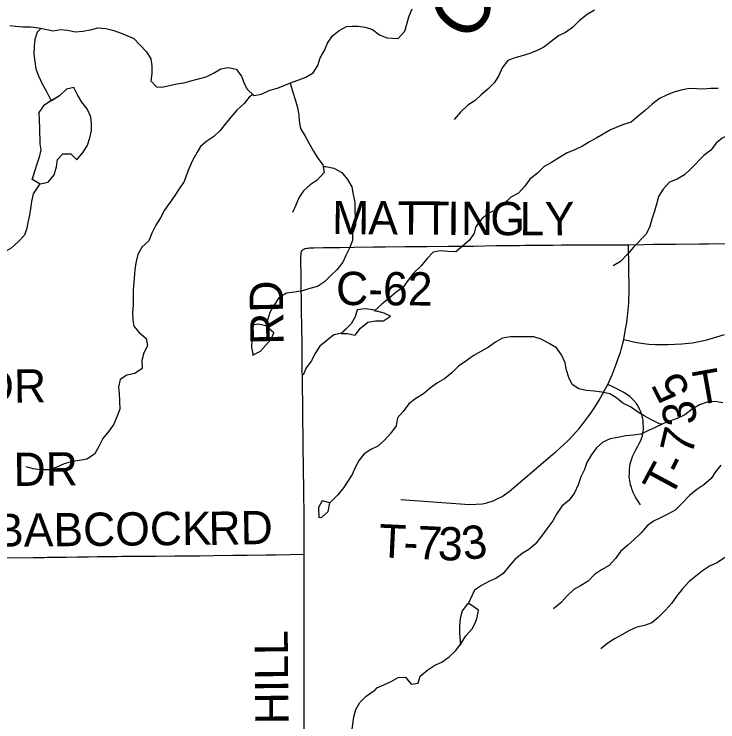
# Model space of a CAD drawing. Extents: x 0 to 34, y 0 to 22.
# Drawn here: x 6.998 to 7.598, y 19.547 to 20.151 of the extents above; entities that cross this region are included whole.
import ezdxf

# ---------------------------------------------------------------- set-up
doc = ezdxf.new("R2010")
doc.units = 0
for name, color, linetype in [('GM_X_County_Road', 7, 'Continuous'), ('GM_X_County_Road_Text', 7, 'Continuous'), ('GM_X_Minor_Lake', 7, 'Continuous'), ('GM_X_Minor_River', 7, 'Continuous'), ('GM_X_Minor_River_Text', 7, 'Continuous'), ('GM_X_Township_Road', 7, 'Continuous'), ('GM_X_Township_Road_Text', 7, 'Continuous')]:
    doc.layers.add(name, color=color, linetype=linetype)

msp = doc.modelspace()

# ---------------------------------------------------------------- linework, layer by layer
at = {"layer": 'GM_X_County_Road'}
for points in [[(7.24366, 19.94905), (7.2443, 19.94977), (7.24497, 19.95028), (7.24573, 19.95066), (7.2465, 19.95087), (7.24755, 19.95108), (7.24865, 19.95117), (7.24983, 19.95125), (7.25135, 19.95129), (7.25355, 19.95136), (7.26175, 19.95146), (7.27591, 19.95168), (7.28804, 19.95193), (7.3046, 19.95214), (7.31483, 19.95227), (7.33145, 19.95233), (7.34095, 19.95239), (7.35041, 19.95248), (7.36812, 19.95265), (7.37995, 19.95273), (7.38993, 19.95286), (7.4089, 19.95317), (7.41423, 19.95323), (7.42078, 19.9533), (7.42902, 19.95345), (7.43371, 19.95349), (7.4425, 19.95353), (7.45021, 19.95362), (7.4575, 19.95366), (7.46507, 19.95374), (7.49066, 19.95378), (7.51308, 19.95396), (7.51899, 19.95401), (7.52228, 19.95401), (7.53535, 19.95425), (7.54364, 19.95433), (7.5629, 19.95456), (7.58271, 19.95464), (7.59039, 19.95474), (7.61189, 19.95488)], [(7.24535, 19.6897), (7.24527, 19.72849), (7.24514, 19.7375), (7.24502, 19.74903), (7.24485, 19.75841), (7.24463, 19.76813), (7.24451, 19.77743), (7.24438, 19.78796), (7.24417, 19.80697), (7.24408, 19.8232), (7.24396, 19.82721), (7.24379, 19.83918), (7.24366, 19.8483), (7.24362, 19.85452), (7.24349, 19.86969), (7.24307, 19.89779), (7.24278, 19.92585), (7.24248, 19.94187), (7.24269, 19.9472), (7.24311, 19.94821), (7.24366, 19.94905)], [(7.2459, 19.17375), (7.24566, 19.20527), (7.24553, 19.29971), (7.2454, 19.39006), (7.24549, 19.40607), (7.24531, 19.49947), (7.24522, 19.61935), (7.24535, 19.65145), (7.24535, 19.6897)]]:
    msp.add_lwpolyline(points, dxfattribs=at)
at = {"layer": 'GM_X_Minor_Lake'}
for points in [[(7.01291, 20.01009), (7.01989, 20.00585), (7.02669, 20.0073), (7.03189, 20.01367), (7.03384, 20.02055), (7.03467, 20.02684), (7.03933, 20.03167), (7.04597, 20.03161), (7.05119, 20.02657), (7.05657, 20.03294), (7.06026, 20.0389), (7.06241, 20.04521), (7.06363, 20.05151), (7.06371, 20.05721), (7.06303, 20.06328), (7.06006, 20.06987), (7.0554, 20.07568), (7.05186, 20.08207), (7.04852, 20.08809), (7.04229, 20.08665), (7.03632, 20.08102), (7.02957, 20.07691)], [(7.01307, 20.00999), (7.01989, 20.00585), (7.02669, 20.0073), (7.03189, 20.01367), (7.03384, 20.02055), (7.03467, 20.02684), (7.03933, 20.03167), (7.04597, 20.03161), (7.05119, 20.02657), (7.05657, 20.03294), (7.06026, 20.0389), (7.06241, 20.04521), (7.06363, 20.05151), (7.06371, 20.05721), (7.06303, 20.06328), (7.06006, 20.06987), (7.0554, 20.07568), (7.05186, 20.08207), (7.04852, 20.08809), (7.04229, 20.08665), (7.03632, 20.08102), (7.02732, 20.07554)], [(7.02732, 20.07554), (7.02282, 20.07241), (7.01875, 20.06682), (7.01907, 20.05999), (7.01938, 20.05353), (7.01963, 20.04005), (7.02048, 20.03512), (7.01908, 20.02864), (7.01711, 20.02271), (7.01514, 20.0164), (7.01307, 20.00999)], [(7.02956, 20.0771), (7.02282, 20.07241), (7.01875, 20.06682), (7.01907, 20.05999), (7.01938, 20.05353), (7.01963, 20.04005), (7.02048, 20.03512), (7.01908, 20.02864), (7.01711, 20.02271), (7.01514, 20.0164), (7.01316, 20.01028)], [(7.30537, 19.89772), (7.30384, 19.89845), (7.297, 19.89927), (7.29056, 19.89839), (7.28878, 19.89228), (7.28528, 19.88632), (7.27687, 19.87814)], [(7.27687, 19.87832), (7.28202, 19.87809), (7.28888, 19.8767), (7.29351, 19.88286), (7.29968, 19.88773), (7.30611, 19.88899), (7.31294, 19.88912), (7.31894, 19.89284), (7.31357, 19.89559), (7.30501, 19.89743)], [(7.30537, 19.89772), (7.30384, 19.89845), (7.297, 19.89927), (7.29056, 19.89839), (7.28878, 19.89228), (7.28528, 19.88632), (7.27704, 19.87831)], [(7.27704, 19.87831), (7.28202, 19.87809), (7.28888, 19.8767), (7.29351, 19.88286), (7.29968, 19.88773), (7.30611, 19.88899), (7.31294, 19.88912), (7.31894, 19.89284), (7.31357, 19.89559), (7.30537, 19.89772)], [(7.21262, 19.88471), (7.20635, 19.88618), (7.19974, 19.88492), (7.20081, 19.87848), (7.20073, 19.87239), (7.20046, 19.86631), (7.20167, 19.85994)], [(7.21262, 19.88471), (7.20635, 19.88618), (7.19974, 19.88492), (7.20081, 19.87848), (7.20073, 19.87239), (7.20046, 19.86631), (7.20173, 19.85968)], [(7.20129, 19.85976), (7.20792, 19.86303), (7.2122, 19.86786), (7.21722, 19.87327), (7.21935, 19.87887), (7.21298, 19.88506)], [(7.20167, 19.85994), (7.20792, 19.86303), (7.2122, 19.86786), (7.21722, 19.87327), (7.21935, 19.87887), (7.21262, 19.88471)], [(7.26715, 19.73367), (7.26052, 19.73518), (7.25746, 19.7296), (7.25781, 19.72122)], [(7.2671, 19.73368), (7.26052, 19.73518), (7.25746, 19.7296), (7.25781, 19.72122)], [(7.25775, 19.72122), (7.26046, 19.72129), (7.26587, 19.72633), (7.26716, 19.73368)], [(7.25781, 19.72122), (7.26046, 19.72129), (7.26587, 19.72633), (7.26715, 19.73367)], [(7.38668, 19.6471), (7.3846, 19.6474), (7.38016, 19.64143), (7.37857, 19.63494), (7.37793, 19.62866), (7.37786, 19.62219), (7.37869, 19.61229)], [(7.38689, 19.64707), (7.3846, 19.6474), (7.38016, 19.64143), (7.37857, 19.63494), (7.37793, 19.62866), (7.37786, 19.62219), (7.37862, 19.61316)], [(7.37869, 19.61229), (7.37953, 19.61405), (7.38322, 19.62001), (7.38861, 19.626), (7.39117, 19.6308), (7.39298, 19.63559), (7.39419, 19.64207), (7.38668, 19.6471)], [(7.3788, 19.61252), (7.37953, 19.61405), (7.38322, 19.62001), (7.38861, 19.626), (7.39117, 19.6308), (7.39298, 19.63559), (7.39419, 19.64207), (7.38671, 19.64708)]]:
    msp.add_lwpolyline(points, dxfattribs=at)
at = {"layer": 'GM_X_Minor_River'}
for points in [[(7.20234, 20.08127), (7.20896, 20.08253), (7.21592, 20.08589), (7.22253, 20.08753), (7.22874, 20.09031), (7.23496, 20.09271), (7.24061, 20.09471), (7.24664, 20.0971), (7.25302, 20.10064), (7.25689, 20.10699), (7.25885, 20.11367), (7.26253, 20.11982), (7.26507, 20.12614), (7.26951, 20.13231), (7.27531, 20.13697), (7.2815, 20.14032), (7.28624, 20.1406), (7.29099, 20.1405), (7.29726, 20.13985), (7.30356, 20.13769), (7.30972, 20.13325), (7.31584, 20.1307), (7.32059, 20.13041), (7.32553, 20.13012), (7.3311, 20.1363), (7.33308, 20.14223), (7.33467, 20.14853), (7.33739, 20.15542)], [(7.49319, 20.15433), (7.48681, 20.15041), (7.48026, 20.14535), (7.47449, 20.13954), (7.4685, 20.13506), (7.46229, 20.13228), (7.44995, 20.12255), (7.44431, 20.11979), (7.4379, 20.1172), (7.4313, 20.11518), (7.42507, 20.11354), (7.41904, 20.11115), (7.41441, 20.10498), (7.4115, 20.09846), (7.40781, 20.0925), (7.40223, 20.0867), (7.39644, 20.08184), (7.39122, 20.07699), (7.38503, 20.07308), (7.37868, 20.06726), (7.37349, 20.06089)], [(6.99403, 20.14105), (6.99897, 20.14057), (7.00506, 20.13992), (7.01189, 20.13986), (7.01836, 20.13903), (7.02426, 20.138), (7.03111, 20.13661), (7.03736, 20.13767), (7.04344, 20.13703), (7.04992, 20.13563), (7.05635, 20.13632), (7.06279, 20.13739), (7.06921, 20.13903), (7.07605, 20.13858), (7.08272, 20.137), (7.08903, 20.13445), (7.0938, 20.13264), (7.09974, 20.1299), (7.10496, 20.12468), (7.11076, 20.11871), (7.11448, 20.11269), (7.11535, 20.10663), (7.11528, 20.10017), (7.11445, 20.09388), (7.1191, 20.08865), (7.12385, 20.08835), (7.13027, 20.09), (7.13669, 20.09144), (7.14256, 20.09232), (7.1486, 20.09376), (7.15521, 20.09559), (7.16163, 20.09723), (7.16783, 20.10039), (7.17421, 20.10412), (7.18045, 20.10537), (7.18712, 20.10379), (7.19179, 20.09779), (7.19418, 20.09157), (7.19674, 20.08667), (7.20234, 20.08127)], [(7.02008, 20.1383), (7.01747, 20.1354), (7.01531, 20.12928), (7.01466, 20.12338), (7.0146, 20.11673), (7.01529, 20.11028), (7.01616, 20.10402), (7.01836, 20.09817), (7.02132, 20.09177), (7.02505, 20.08537), (7.02917, 20.0767)], [(7.23345, 20.09211), (7.23366, 20.09097), (7.23549, 20.08416), (7.23751, 20.07793), (7.23953, 20.07113), (7.2406, 20.06469), (7.24088, 20.05975), (7.24214, 20.05331), (7.24625, 20.04655), (7.24959, 20.04034), (7.25313, 20.03394), (7.25684, 20.02793), (7.26113, 20.02212), (7.26239, 20.01549), (7.25644, 20.00911), (7.25044, 20.0052), (7.24465, 19.99996), (7.24078, 19.994), (7.23824, 19.98787), (7.23532, 19.98135)], [(7.59879, 20.08732), (7.59234, 20.08739), (7.58552, 20.08688), (7.58077, 20.08698), (7.57394, 20.08724), (7.56713, 20.08597), (7.5609, 20.08433), (7.55469, 20.08156), (7.54867, 20.07879), (7.5423, 20.07411), (7.53671, 20.06887), (7.53054, 20.06382), (7.52438, 20.05857), (7.51796, 20.05655), (7.51175, 20.05396), (7.50685, 20.05197), (7.50066, 20.04844), (7.49503, 20.0451), (7.48902, 20.04195), (7.48282, 20.03822), (7.47624, 20.03487), (7.46984, 20.03247), (7.46327, 20.02836), (7.45652, 20.02405), (7.45014, 20.0207), (7.44436, 20.01508), (7.438, 20.00983), (7.43356, 20.00386), (7.42836, 19.99806), (7.42178, 19.99452), (7.416, 19.98928), (7.40965, 19.98384), (7.40325, 19.98106), (7.39689, 19.976), (7.39189, 19.96964), (7.39029, 19.96372), (7.38604, 19.95756), (7.38044, 19.9527), (7.37483, 19.94804), (7.368, 19.94829), (7.36173, 19.94874), (7.35549, 19.94749), (7.35009, 19.94188), (7.34527, 19.9359), (7.33855, 19.92969), (7.33411, 19.92372), (7.32986, 19.91775), (7.32349, 19.91326), (7.31752, 19.90801), (7.31153, 19.90315), (7.30556, 19.89772)], [(7.20139, 20.08213), (7.19838, 20.07986), (7.19393, 20.07446), (7.18777, 20.06883), (7.18257, 20.06285), (7.17794, 20.05687), (7.17368, 20.05147), (7.16808, 20.04623), (7.16208, 20.04251), (7.15685, 20.03785), (7.15391, 20.03305), (7.14987, 20.02594), (7.14678, 20.01866), (7.14442, 20.01273), (7.1428, 20.00795), (7.13855, 20.00179), (7.13431, 19.99506), (7.12618, 19.9835), (7.12251, 19.97697), (7.11864, 19.97063), (7.11535, 19.96392), (7.11262, 19.95741), (7.10666, 19.95178), (7.10336, 19.94564), (7.10195, 19.93972), (7.10074, 19.93324), (7.10045, 19.92848), (7.09981, 19.92201), (7.09937, 19.91516), (7.0993, 19.90851), (7.09923, 19.90243), (7.09878, 19.89615), (7.0989, 19.88969), (7.09994, 19.88458), (7.10402, 19.87933), (7.11038, 19.87394), (7.11164, 19.86769), (7.10834, 19.86155), (7.10675, 19.85506), (7.10707, 19.84823), (7.1007, 19.84393), (7.09389, 19.84266), (7.08827, 19.83894), (7.08687, 19.83265), (7.08735, 19.82696), (7.08766, 19.8205), (7.08779, 19.81366), (7.08544, 19.80716), (7.08271, 19.80083), (7.07847, 19.79468), (7.07346, 19.7885), (7.06998, 19.78178), (7.0663, 19.77525), (7.05975, 19.77076), (7.05312, 19.76988), (7.04631, 19.76861), (7.04047, 19.76679), (7.03426, 19.76402), (7.02728, 19.7618), (7.02045, 19.76167), (7.01398, 19.7625), (7.00787, 19.76448)], [(7.61368, 20.05003), (7.61341, 20.04988), (7.60806, 20.04778), (7.60224, 20.04482), (7.597, 20.04073), (7.59256, 20.03476), (7.58657, 20.03008), (7.5754, 20.01885), (7.56999, 20.01362), (7.56361, 20.01008), (7.55721, 20.0073), (7.55181, 20.0015), (7.54776, 19.99516), (7.54617, 19.98866), (7.54439, 19.98255), (7.54224, 19.97586), (7.54027, 19.96955), (7.53716, 19.96303), (7.52655, 19.952), (7.52135, 19.94583), (7.5154, 19.93963), (7.50901, 19.93609)], [(7.2621, 20.02062), (7.26381, 20.02084), (7.27066, 20.01945), (7.27737, 20.01577), (7.28223, 20.00959), (7.28595, 20.00339), (7.28721, 19.99676), (7.28867, 19.98995), (7.2886, 19.98368), (7.28891, 19.97684), (7.28903, 19.97038), (7.28669, 19.96369), (7.28642, 19.9576), (7.28389, 19.95109), (7.28097, 19.94477), (7.27823, 19.93902), (7.2736, 19.93285), (7.268, 19.92781), (7.26261, 19.92219), (7.25661, 19.91828), (7.25019, 19.91664), (7.24377, 19.91462), (7.23715, 19.91355), (7.23015, 19.91266), (7.22377, 19.90855), (7.21934, 19.90219), (7.21603, 19.89624), (7.21262, 19.88471)], [(7.01973, 20.00586), (7.01378, 19.99737), (7.01258, 19.99089), (7.01174, 19.98479), (7.0109, 19.97907), (7.00949, 19.97297), (7.00863, 19.9682), (7.00666, 19.96208), (7.00107, 19.95647), (6.9951, 19.95104), (6.9891, 19.9475), (6.9835, 19.94227), (6.97907, 19.93573), (6.97802, 19.93095), (6.97815, 19.92412), (6.97865, 19.91728), (6.98068, 19.91048)], [(7.27746, 19.87838), (7.27066, 19.87712), (7.25869, 19.86739), (7.25445, 19.86085), (7.25153, 19.85472), (7.24689, 19.84893), (7.24435, 19.84261)], [(7.55081, 19.80081), (7.54852, 19.80115), (7.54182, 19.80444), (7.5355, 19.80775), (7.52974, 19.81125), (7.52378, 19.81551), (7.51746, 19.81881), (7.51226, 19.8229), (7.50631, 19.82659), (7.49945, 19.82798), (7.49298, 19.82881), (7.48633, 19.82964), (7.47985, 19.83084), (7.47409, 19.83454), (7.47113, 19.84075), (7.46931, 19.84699), (7.46805, 19.85324), (7.46489, 19.85983), (7.46079, 19.86603), (7.45447, 19.86952), (7.44756, 19.87338), (7.44127, 19.87535), (7.43443, 19.87542), (7.42799, 19.8753), (7.42153, 19.87537), (7.41473, 19.8741), (7.40872, 19.87076), (7.40272, 19.86665), (7.39615, 19.86273), (7.38958, 19.859), (7.38321, 19.8547), (7.37703, 19.8504), (7.37144, 19.8446), (7.36509, 19.83954), (7.35908, 19.8362), (7.35328, 19.83191), (7.3473, 19.82667), (7.34073, 19.82274), (7.33456, 19.81826), (7.32974, 19.81171), (7.32511, 19.80611), (7.32371, 19.79943), (7.31928, 19.79308), (7.3137, 19.78689), (7.3081, 19.78185), (7.30227, 19.77908), (7.29646, 19.77536), (7.29219, 19.77015), (7.28907, 19.76439), (7.28616, 19.75788), (7.28192, 19.75115), (7.27897, 19.74634), (7.27396, 19.74055), (7.26721, 19.73365)], [(7.60265, 19.81907), (7.59617, 19.82009), (7.58935, 19.81958), (7.58295, 19.81718), (7.57656, 19.81364), (7.5702, 19.80877), (7.56381, 19.80561), (7.55721, 19.8034), (7.55156, 19.80102), (7.54498, 19.79785), (7.53933, 19.79528), (7.53275, 19.7923), (7.52613, 19.79142), (7.51987, 19.79092), (7.51307, 19.78947), (7.50664, 19.78821), (7.50024, 19.78543), (7.49483, 19.78058), (7.49021, 19.77422), (7.48671, 19.76807), (7.48455, 19.76195), (7.48163, 19.75582), (7.47929, 19.74893), (7.476, 19.74203), (7.47156, 19.73587), (7.46521, 19.73081), (7.46059, 19.72407), (7.45748, 19.71812), (7.45248, 19.71138), (7.44785, 19.70502), (7.44247, 19.69846), (7.43706, 19.6938), (7.43143, 19.69046), (7.42526, 19.68522), (7.42006, 19.67923), (7.41524, 19.67325), (7.40905, 19.66914), (7.40303, 19.66656), (7.39665, 19.66302), (7.39084, 19.65892), (7.38509, 19.64685)], [(7.60098, 19.76583), (7.59653, 19.76005), (7.59266, 19.75427), (7.58649, 19.74903), (7.58049, 19.74512), (7.57414, 19.73987), (7.56838, 19.73349), (7.56204, 19.72748), (7.55584, 19.72394), (7.54945, 19.72078), (7.54343, 19.71782), (7.53819, 19.71392), (7.53299, 19.70812), (7.5274, 19.70251), (7.52161, 19.69746), (7.51545, 19.69203), (7.5112, 19.68606), (7.5058, 19.68025), (7.49923, 19.67652), (7.49324, 19.67242), (7.48765, 19.6668), (7.48128, 19.66269), (7.47545, 19.65955), (7.46986, 19.65431), (7.46484, 19.64852), (7.4583, 19.64307)], [(7.61617, 19.69409), (7.61636, 19.6941), (7.60997, 19.69056), (7.60398, 19.68626), (7.5976, 19.68234), (7.59139, 19.67957), (7.58539, 19.67566), (7.5796, 19.67099), (7.57399, 19.66632), (7.56841, 19.66014), (7.56359, 19.65416), (7.55878, 19.6478), (7.55376, 19.642), (7.54743, 19.63561), (7.54201, 19.63114), (7.53579, 19.62875), (7.52937, 19.62748), (7.52316, 19.62471), (7.5164, 19.62097), (7.5102, 19.61744), (7.50457, 19.61391), (7.49859, 19.60905)], [(7.30591, 19.57354), (7.3072, 19.57565), (7.31341, 19.57824), (7.31943, 19.58101), (7.32544, 19.58454), (7.33188, 19.58485), (7.33674, 19.57867), (7.34261, 19.57954), (7.34439, 19.58565), (7.35074, 19.59109), (7.35674, 19.59501), (7.36276, 19.59759), (7.36913, 19.60227), (7.37453, 19.60731), (7.37917, 19.6131)], [(7.22827, 19.48144), (7.24372, 19.49143), (7.24975, 19.49249), (7.25576, 19.49525), (7.26173, 19.49953), (7.26712, 19.50512), (7.26889, 19.5118), (7.27108, 19.51658), (7.27743, 19.52124), (7.28226, 19.52607), (7.28405, 19.53217), (7.28602, 19.53847), (7.28686, 19.54437), (7.28769, 19.55102), (7.28928, 19.55731), (7.29277, 19.56325), (7.29835, 19.56848), (7.30565, 19.57377)]]:
    msp.add_lwpolyline(points, dxfattribs=at)
at = {"layer": 'GM_X_Township_Road'}
for points in [[(7.3277, 19.73635), (7.38656, 19.73228), (7.39744, 19.73275), (7.4012, 19.73353), (7.4066, 19.73518), (7.41074, 19.73719), (7.41439, 19.73908), (7.42039, 19.7434), (7.45739, 19.77486), (7.46029, 19.77728), (7.46319, 19.77987), (7.4671, 19.78347), (7.47062, 19.78684), (7.47532, 19.79168), (7.48001, 19.79701), (7.48314, 19.80092), (7.48745, 19.80663), (7.4905, 19.81094), (7.49394, 19.8161), (7.49715, 19.82127), (7.50004, 19.8263), (7.50238, 19.83053), (7.5046, 19.83475), (7.50819, 19.84295), (7.50991, 19.84733), (7.51163, 19.85187), (7.51343, 19.85688), (7.51523, 19.8622), (7.51591, 19.86464), (7.51672, 19.86745), (7.51741, 19.87001), (7.51821, 19.87293), (7.51977, 19.88177), (7.52079, 19.88748), (7.52165, 19.89547), (7.52236, 19.90416), (7.52267, 19.91566), (7.52228, 19.95401)], [(7.51821, 19.87293), (7.52431, 19.87152), (7.52776, 19.87081), (7.53292, 19.86987), (7.53965, 19.86909), (7.54529, 19.86878), (7.55593, 19.86886), (7.5618, 19.86909), (7.56775, 19.86933), (7.57339, 19.86995), (7.57683, 19.87034), (7.58106, 19.87105), (7.58505, 19.87191), (7.5892, 19.87285), (7.59757, 19.87527), (7.60407, 19.87723)], [(7.53239, 19.73183), (7.52975, 19.73575), (7.52821, 19.73844), (7.52621, 19.74253), (7.52532, 19.74483), (7.52464, 19.74692), (7.52404, 19.74897), (7.52353, 19.75089), (7.52323, 19.75276), (7.52301, 19.75434), (7.52289, 19.7557), (7.52293, 19.75877), (7.5231, 19.7624), (7.52335, 19.76457), (7.5237, 19.76683), (7.5241, 19.76848), (7.52464, 19.77028), (7.52566, 19.7731), (7.52724, 19.77655), (7.52867, 19.77941), (7.53026, 19.78205), (7.53141, 19.78423), (7.53252, 19.78636), (7.53338, 19.78866), (7.53402, 19.79092), (7.53452, 19.79301), (7.53478, 19.79484), (7.53491, 19.79655), (7.53474, 19.80324), (7.53435, 19.80571), (7.53393, 19.80742), (7.53355, 19.80891), (7.53265, 19.81134), (7.53167, 19.81364), (7.53039, 19.81603), (7.52894, 19.81829), (7.52638, 19.82136), (7.52357, 19.82413), (7.5205, 19.82639), (7.51769, 19.82822), (7.51402, 19.8301), (7.50945, 19.83235), (7.5046, 19.83475)], [(6.70594, 19.68226), (6.72858, 19.68257), (6.74669, 19.68298), (6.76893, 19.68327), (6.78988, 19.68346), (6.80899, 19.6839), (6.82784, 19.68412), (6.84666, 19.68441), (6.86584, 19.68467), (6.88487, 19.68493), (6.90358, 19.68526), (6.92997, 19.68577), (6.93849, 19.68597), (6.98096, 19.6866), (6.99053, 19.6867), (7.01392, 19.68696), (7.0235, 19.68707), (7.026, 19.68711)], [(7.026, 19.68711), (7.0305, 19.68717), (7.04215, 19.68734), (7.05163, 19.68746), (7.06106, 19.68758), (7.06885, 19.68768), (7.08005, 19.68783), (7.08521, 19.68789), (7.08952, 19.68795), (7.09898, 19.68807), (7.1086, 19.68809), (7.1184, 19.68814), (7.13484, 19.68822), (7.14414, 19.6883), (7.1566, 19.68847), (7.16789, 19.68864), (7.18433, 19.68889), (7.19667, 19.68902), (7.21285, 19.68919), (7.22093, 19.68928), (7.24535, 19.6897)]]:
    msp.add_lwpolyline(points, dxfattribs=at)

# ---------------------------------------------------------------- texts
at = {"layer": 'GM_X_County_Road_Text'}
for s, height, rotation, p in [('M', 0.02841, 359.63375, (7.2691, 19.96305)), ('A', 0.02841, 359.63207, (7.29993, 19.96285)), ('T', 0.02841, 359.63628, (7.32493, 19.96269)), ('T', 0.02841, 359.63143, (7.34618, 19.96256)), ('I', 0.02841, 359.63624, (7.36743, 19.96242)), ('N', 0.02841, 359.63207, (7.3791, 19.96234)), ('G', 0.02841, 359.63584, (7.4041, 19.96218)), ('L', 0.02841, 359.679, (7.42912, 19.96203)), ('Y', 0.02841, 0.67585, (7.45091, 19.96191)), ('C-62', 0.028409, 359.6571, (7.27248, 19.90251)), ('RD', 0.028409, 90.98722, (7.22786, 19.86876)), ('HILL', 0.028409, 90.56669, (7.23203, 19.54465))]:
    msp.add_text(s, height=height, rotation=rotation, dxfattribs=at).set_placement(p)
at = {"layer": 'GM_X_Minor_River_Text'}
msp.add_text('Creek', height=0.047376, rotation=51.98786, dxfattribs=at).set_placement((7.38434, 20.12456))
at = {"layer": 'GM_X_Township_Road_Text'}
for s, height, rotation, p in [('DR', 0.028409, 0.49795, (6.97018, 19.81887)), ('T', 0.02841, 10.19368, (7.58054, 19.81675)), ('5', 0.02841, 117.18387, (7.57554, 19.82889)), ('3', 0.02841, 97.43061, (7.58097, 19.80139)), ('7', 0.02841, 76.56243, (7.57631, 19.77317)), ('MARLAND DR', 0.028409, 0.61587, (6.80102, 19.74586)), ('T', 0.02841, 61.62929, (7.55811, 19.73652)), ('-', 0.02841, 63.36514, (7.56864, 19.75605)), ('BABCOCK', 0.028409, 0.56752, (6.98067, 19.69597)), ('RD', 0.028409, 0.98724, (7.16384, 19.69762)), ('T', 0.02841, 357.32913, (7.3084, 19.6872)), ('3', 0.02841, 7.8574, (7.38193, 19.68451)), ('7', 0.02841, 357.40655, (7.34132, 19.68567)), ('3', 0.02841, 357.95455, (7.3591, 19.68486)), ('-', 0.02841, 357.33589, (7.32963, 19.68621))]:
    msp.add_text(s, height=height, rotation=rotation, dxfattribs=at).set_placement(p)

doc.saveas('drawing.dxf')
